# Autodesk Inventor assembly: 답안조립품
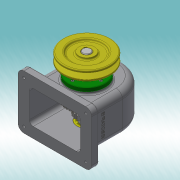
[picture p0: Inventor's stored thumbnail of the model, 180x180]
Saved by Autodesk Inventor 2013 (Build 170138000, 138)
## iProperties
Created: 2016-10
Part Number: 답안조립품
Document SubType Name: Assembly
Designer: dgall
Author: dgall
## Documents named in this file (15)
- C:\Users\dgall\Desktop\461007V1011\답안조립품.iam
- C:\Users\dgall\Desktop\461007V1011\본체.ipt
- C:\Users\dgall\Desktop\461007V1011\V-벨트풀리.ipt
- C:\Users\dgall\Desktop\461007V1011\뒤커버.ipt
- C:\Users\dgall\Desktop\461007V1011\멈춤나사 - M4x10.ipt
- C:\Users\dgall\Desktop\461007V1011\베어링 6203.ipt
- C:\Users\dgall\Desktop\461007V1011\볼트 M3 x 8.ipt
- C:\Users\dgall\Desktop\461007V1011\볼트 M3 x 10.ipt
- C:\Users\dgall\Desktop\461007V1011\부시.ipt
- C:\Users\dgall\Desktop\461007V1011\스퍼기어.ipt
- C:\Users\dgall\Desktop\461007V1011\앞커버.ipt
- C:\Users\dgall\Desktop\461007V1011\오일씰 28 40 8.ipt
- C:\Users\dgall\Desktop\461007V1011\축.ipt
- C:\Users\dgall\Desktop\461007V1011\키 - 5 x 5 x 18.ipt
- C:\Users\dgall\Desktop\461007V1011\키 - 6 x 6 x 22.ipt
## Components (9 placed, 3 different names)
1. V-벨트풀리:1
2. ISO 4762 M3 x 10:1
3. ISO 4762 M3 x 10:2
4. ISO 4762 M3 x 10:3
5. ISO 4762 M3 x 10:4
6. ISO 4762 M3 x 8:1
7. ISO 4762 M3 x 8:2
8. ISO 4762 M3 x 8:3
9. ISO 4762 M3 x 8:4
